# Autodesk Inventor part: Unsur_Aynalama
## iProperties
Shininess: 64.0
Length Units: 11269
Angle Units: 11279
Time Units: 11290
Mass Units: 11283
Length Display Precision: 3
Angle Display Precision: 2
Compacted: True
Part Number: Unsur_Aynalama
Document SubType Name: Modeling
Created: 2004-04
Designer: Administrator
Manufacturer: Standard
Standards Organization: Custom
Density: 1 g/cm^3
Density: 0.0
Volumn: 0.0
Area: 0.0
PropertySet Name: Model Information
Control State: 0
Master: False
Checked Out: False
Author: Administrator
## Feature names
1. Extrusion1
2. Hole2
3. Extrusion2
4. Extrusion3
